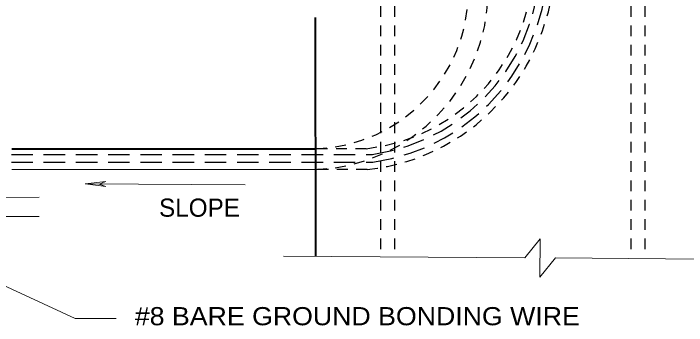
# Model space of a CAD drawing. Extents: x 312583 to 312854, y 144419 to 144597.
# Drawn here: x 312774.81 to 312803, y 144449.04 to 144462.09 of the extents above; entities that cross this region are included whole.
import ezdxf

# ---------------------------------------------------------------- set-up
doc = ezdxf.new("R2010")
doc.units = 0
doc.header["$LTSCALE"] = 0.3
doc.linetypes.add('MEDIUM_DASHED', pattern=[4.5, 3, -1.5])
doc.linetypes.add('SHORT_DASHED', pattern=[2.7, 1.5, -1.2])
doc.layers.add('1', color=7, linetype='Continuous', lineweight=40)
doc.layers.add('2', color=7, linetype='Continuous', lineweight=13)

msp = doc.modelspace()

# ---------------------------------------------------------------- linework, layer by layer
at = {"layer": '1', "linetype": 'SHORT_DASHED', "lineweight": 25}
for p, q in [((312790.1812, 144473.7362), (312790.1812, 144451.9399)), ((312790.7638, 144473.7362), (312790.7638, 144451.9399)), ((312800.6692, 144473.7362), (312800.6692, 144451.9399)), ((312801.2518, 144473.7362), (312801.2518, 144451.9399)), ((312789.5832, 144456.4326), (312787.4825, 144456.4326)), ((312789.6215, 144455.5586), (312787.4825, 144455.5586))]:
    msp.add_line(p, q, dxfattribs=at)
at = {"layer": '1'}
for p, q in [((312787.4825, 144451.9322), (312787.4595, 144461.9219)), ((312774.7405, 144456.4326), (312787.4825, 144456.4326))]:
    msp.add_line(p, q, dxfattribs=at)
at = {"layer": '1', "linetype": 'MEDIUM_DASHED', "lineweight": 25}
for p, q in [((312770.6772, 144456.1949), (312789.8438, 144456.1949)), ((312770.6772, 144455.8729), (312789.8592, 144455.8729))]:
    msp.add_line(p, q, dxfattribs=at)
at = {"layer": '1', "lineweight": 13}
msp.add_line((312774.7405, 144455.5586), (312787.4825, 144455.5586), dxfattribs=at)
at = {"layer": '1', "linetype": 'SHORT_DASHED', "lineweight": 25}
for centre, radius, start, end in [((312788.7032, 144464.2788), 7.8954, 276.39911, 2.59262), ((312788.7032, 144464.2788), 8.7686, 276.02186, 2.58451), ((312787.2543, 144463.0432), 6.6145, 271.97676, 0.18254), ((312787.2007, 144463.0432), 7.4885, 272.15643, 0.16124)]:
    msp.add_arc(centre, radius, start, end, dxfattribs=at)
at = {"layer": '1', "linetype": 'MEDIUM_DASHED', "lineweight": 25}
for radius, start, end in [(8.1634, 278.00735, 2.61493), (8.4852, 277.83918, 2.56745)]:
    msp.add_arc((312788.7032, 144464.2788), radius, start, end, dxfattribs=at)
at = {"layer": '2'}
for p, q in [((312777.8148, 144454.9606), (312778.6812, 144455.0602)), ((312777.8148, 144454.9606), (312784.5155, 144454.9146)), ((312777.8148, 144454.9606), (312778.6812, 144454.8456)), ((312778.6812, 144455.0602), (312778.4052, 144454.9529)), ((312778.6812, 144454.8456), (312778.4052, 144454.9529)), ((312764.4288, 144454.3779), (312775.8828, 144454.4009)), ((312764.0992, 144453.5729), (312775.8828, 144453.5959)), ((312771.1065, 144452.2466), (312777.3932, 144449.3256)), ((312786.1255, 144451.9399), (312796.2302, 144451.8709)), ((312797.5105, 144451.8632), (312805.2232, 144451.8019)), ((312777.3932, 144449.3256), (312779.1105, 144449.3332))]:
    msp.add_line(p, q, dxfattribs=at)
msp.add_lwpolyline([(312796.2302, 144451.8709), (312796.8742, 144452.6606), (312796.8588, 144451.0659), (312797.5105, 144451.8632)], dxfattribs=at)

# ---------------------------------------------------------------- texts
msp.add_text('SLOPE', height=0.76, dxfattribs=at).set_placement((312780.9091, 144453.5872))
at = {"layer": '2', "width": 1.1}
msp.add_text('#8 BARE GROUND BONDING WIRE', height=0.76, dxfattribs=at).set_placement((312779.8968, 144449.0486))

doc.saveas('drawing.dxf')
